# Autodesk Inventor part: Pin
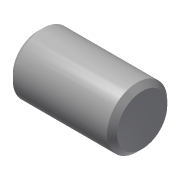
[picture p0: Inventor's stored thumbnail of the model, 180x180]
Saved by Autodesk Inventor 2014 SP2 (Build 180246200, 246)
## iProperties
Created: 2015-04
Part Number: Pin
Material: Steel
Document SubType Name: Modeling
Designer: SFC
Density: 7.85 g/cm^3
Appearance: Steel
Author: SFC
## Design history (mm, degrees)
sketch "Sketch1"
  geometry: L1 (-5.2, 0)-(-5.2, 3); L2 (-5.2, 3)-(5.2, 3); L3 (5.2, 3)-(5.2, 0); L4 (5.2, 0)-(-5.2, 0); 2 further points
  constraints: 8 end point, 2 parallel, 1 coincident, 1 midpoint, 1 perpendicular, 1 vertical
  dimensions: "d0" = 6 diameter of L2 L4; "d1" = 10.4 distance between parallel lines of L3 L1
revolve "Revolution1" sketch "Sketch1" stored, may be unused: angle "d2" = 90 deg
chamfer "Chamfer1" distance "d3" = 0.5; stored, may be unused: second distance "d4" = 2, angle "d5" = 45 deg
body "Solid1"
